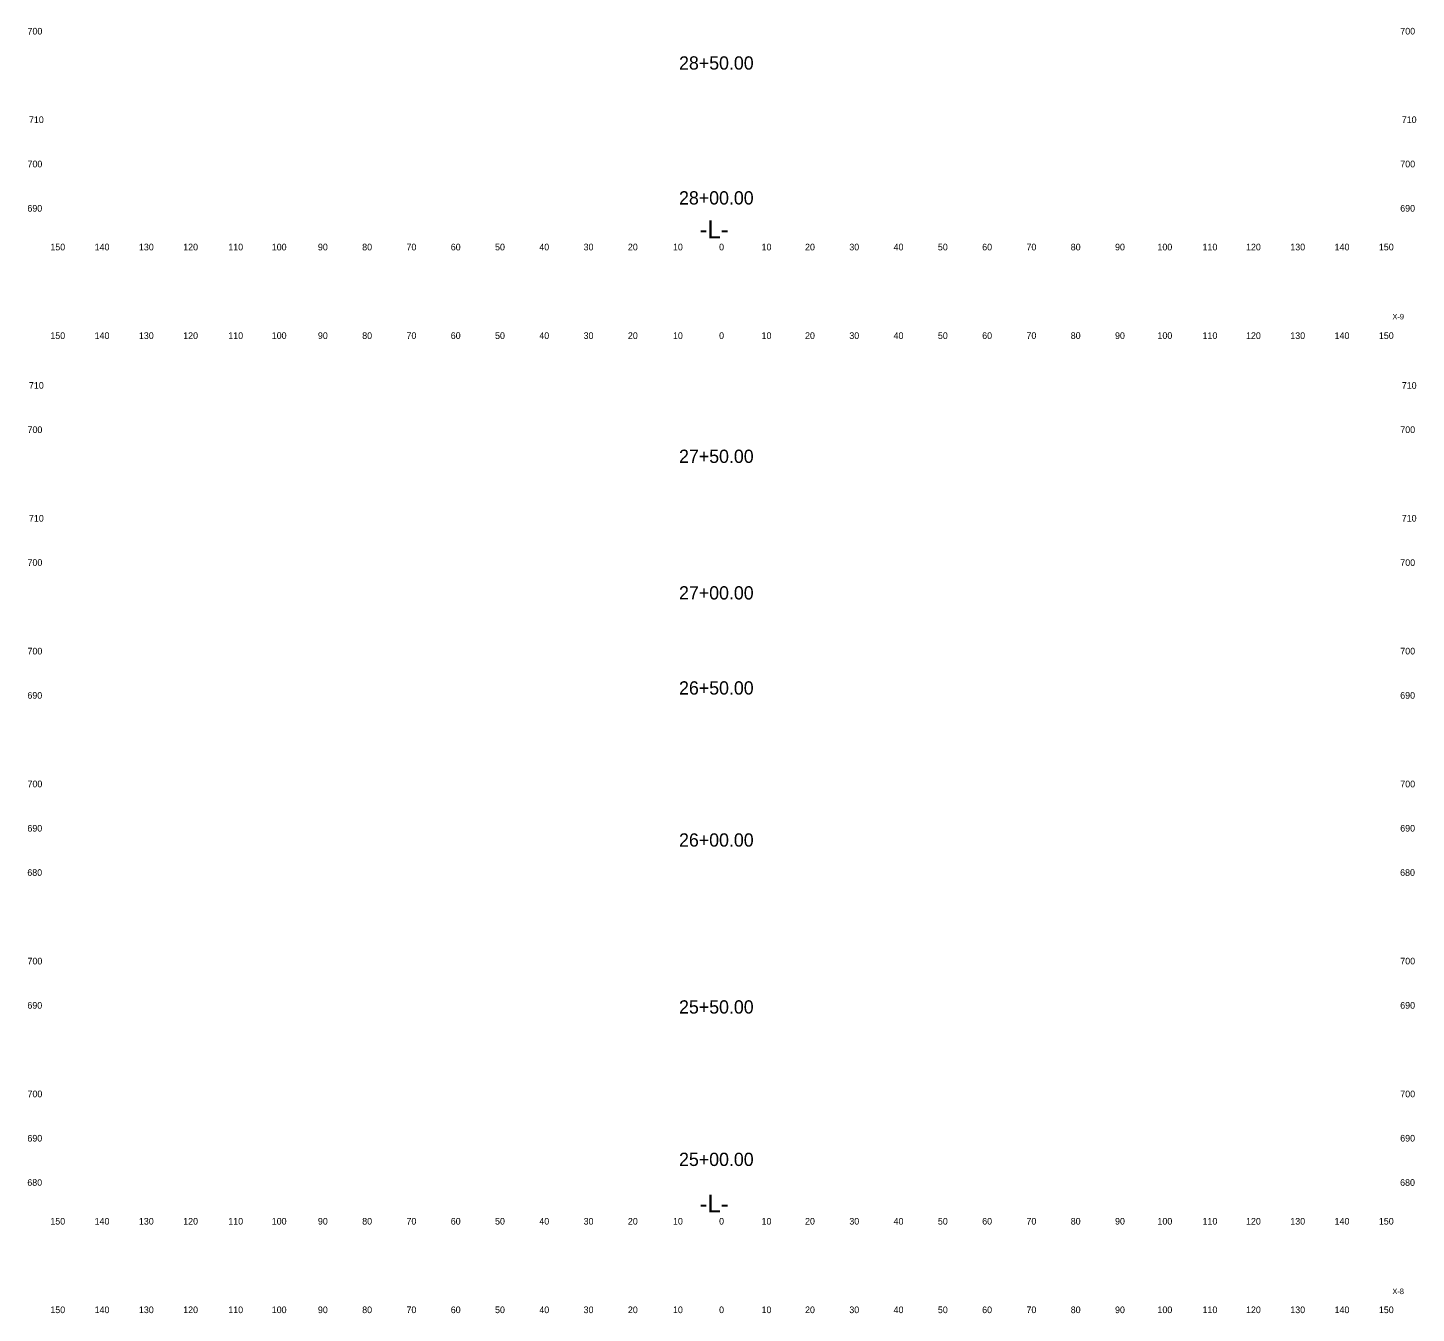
# Model space of a CAD drawing. Extents: x 3 to 317, y 0 to 2407.
# Drawn here: x 3.3 to 316.9, y 1521.2 to 1811.5 of the extents above; entities that cross this region are included whole.
import ezdxf

# ---------------------------------------------------------------- set-up
doc = ezdxf.new("R2010")
doc.units = 0
for name, color, linetype in [('Prop XS Ditch Standard Text', 7, 'Continuous'), ('Prop XS Dump Level', 7, 'Continuous'), ('Prop XS SE Text', 7, 'Continuous'), ('Prop XS Sheet Number', 7, 'Continuous'), ('Prop XS SS Elevation Text', 7, 'Continuous')]:
    doc.layers.add(name, color=color, linetype=linetype)

msp = doc.modelspace()

# ---------------------------------------------------------------- texts
at = {"layer": 'Prop XS Ditch Standard Text'}
for s, p in [('28+50.00', (150.41, 1802.07)), ('28+00.00', (150.41, 1771.61)), ('27+50.00', (150.41, 1713.25)), ('27+00.00', (150.41, 1682.41)), ('26+50.00', (150.41, 1660.94)), ('26+00.00', (150.41, 1626.6)), ('25+50.00', (150.41, 1588.9)), ('25+00.00', (150.41, 1554.48))]:
    msp.add_text(s, height=3, dxfattribs=at).set_placement(p)
at = {"layer": 'Prop XS Dump Level'}
for s, p in [('150', (8.44, 1761.25)), ('140', (18.44, 1761.25)), ('130', (28.44, 1761.25)), ('120', (38.44, 1761.25)), ('110', (48.62, 1761.25)), ('100', (58.44, 1761.25)), ('90', (68.86, 1761.25)), ('80', (78.86, 1761.25)), ('70', (88.86, 1761.25)), ('60', (98.86, 1761.25)), ('50', (108.86, 1761.25)), ('40', (118.86, 1761.25)), ('30', (128.86, 1761.25)), ('20', (138.86, 1761.25)), ('10', (149.04, 1761.25)), ('0', (159.45, 1761.25)), ('10', (169.04, 1761.25)), ('20', (178.86, 1761.25)), ('30', (188.86, 1761.25)), ('40', (198.86, 1761.25)), ('50', (208.86, 1761.25)), ('60', (218.86, 1761.25)), ('70', (228.86, 1761.25)), ('80', (238.86, 1761.25)), ('90', (248.86, 1761.25)), ('100', (258.44, 1761.25)), ('110', (268.62, 1761.25)), ('120', (278.44, 1761.25)), ('130', (288.44, 1761.25)), ('140', (298.44, 1761.25)), ('150', (308.44, 1761.25)), ('150', (8.44, 1741.25)), ('140', (18.44, 1741.25)), ('130', (28.44, 1741.25)), ('120', (38.44, 1741.25)), ('110', (48.62, 1741.25)), ('100', (58.44, 1741.25)), ('90', (68.86, 1741.25)), ('80', (78.86, 1741.25)), ('70', (88.86, 1741.25)), ('60', (98.86, 1741.25)), ('50', (108.86, 1741.25)), ('40', (118.86, 1741.25)), ('30', (128.86, 1741.25)), ('20', (138.86, 1741.25)), ('10', (149.04, 1741.25)), ('0', (159.45, 1741.25)), ('10', (169.04, 1741.25)), ('20', (178.86, 1741.25)), ('30', (188.86, 1741.25)), ('40', (198.86, 1741.25)), ('50', (208.86, 1741.25)), ('60', (218.86, 1741.25)), ('70', (228.86, 1741.25)), ('80', (238.86, 1741.25)), ('90', (248.86, 1741.25)), ('100', (258.44, 1741.25)), ('110', (268.62, 1741.25)), ('120', (278.44, 1741.25)), ('130', (288.44, 1741.25)), ('140', (298.44, 1741.25)), ('150', (308.44, 1741.25)), ('150', (8.44, 1541.25)), ('140', (18.44, 1541.25)), ('130', (28.44, 1541.25)), ('120', (38.44, 1541.25)), ('110', (48.62, 1541.25)), ('100', (58.44, 1541.25)), ('90', (68.86, 1541.25)), ('80', (78.86, 1541.25)), ('70', (88.86, 1541.25)), ('60', (98.86, 1541.25)), ('50', (108.86, 1541.25)), ('40', (118.86, 1541.25)), ('30', (128.86, 1541.25)), ('20', (138.86, 1541.25)), ('10', (149.04, 1541.25)), ('0', (159.45, 1541.25)), ('10', (169.04, 1541.25)), ('20', (178.86, 1541.25)), ('30', (188.86, 1541.25)), ('40', (198.86, 1541.25)), ('50', (208.86, 1541.25)), ('60', (218.86, 1541.25)), ('70', (228.86, 1541.25)), ('80', (238.86, 1541.25)), ('90', (248.86, 1541.25)), ('100', (258.44, 1541.25)), ('110', (268.62, 1541.25)), ('120', (278.44, 1541.25)), ('130', (288.44, 1541.25)), ('140', (298.44, 1541.25)), ('150', (308.44, 1541.25)), ('150', (8.44, 1521.25)), ('140', (18.44, 1521.25)), ('130', (28.44, 1521.25)), ('120', (38.44, 1521.25)), ('110', (48.62, 1521.25)), ('100', (58.44, 1521.25)), ('90', (68.86, 1521.25)), ('80', (78.86, 1521.25)), ('70', (88.86, 1521.25)), ('60', (98.86, 1521.25)), ('50', (108.86, 1521.25)), ('40', (118.86, 1521.25)), ('30', (128.86, 1521.25)), ('20', (138.86, 1521.25)), ('10', (149.04, 1521.25)), ('0', (159.45, 1521.25)), ('10', (169.04, 1521.25)), ('20', (178.86, 1521.25)), ('30', (188.86, 1521.25)), ('40', (198.86, 1521.25)), ('50', (208.86, 1521.25)), ('60', (218.86, 1521.25)), ('70', (228.86, 1521.25)), ('80', (238.86, 1521.25)), ('90', (248.86, 1521.25)), ('100', (258.44, 1521.25)), ('110', (268.62, 1521.25)), ('120', (278.44, 1521.25)), ('130', (288.44, 1521.25)), ('140', (298.44, 1521.25)), ('150', (308.44, 1521.25))]:
    msp.add_text(s, height=1.5, dxfattribs=at).set_placement(p)
at = {"layer": 'Prop XS SE Text'}
for s, p in [('700', (3.28, 1810)), ('700', (313.28, 1810)), ('710', (3.61, 1790)), ('710', (313.61, 1790)), ('700', (3.28, 1780)), ('700', (313.28, 1780)), ('690', (3.26, 1770)), ('690', (313.26, 1770)), ('710', (3.61, 1730)), ('710', (313.61, 1730)), ('700', (3.28, 1720)), ('700', (313.28, 1720)), ('710', (3.61, 1700)), ('710', (313.61, 1700)), ('700', (3.28, 1690)), ('700', (313.28, 1690)), ('700', (3.28, 1670)), ('700', (313.28, 1670)), ('690', (3.26, 1660)), ('690', (313.26, 1660)), ('700', (3.28, 1640)), ('700', (313.28, 1640)), ('690', (3.26, 1630)), ('690', (313.26, 1630)), ('680', (3.24, 1620)), ('680', (313.24, 1620)), ('700', (3.28, 1600)), ('700', (313.28, 1600)), ('690', (3.26, 1590)), ('690', (313.26, 1590)), ('700', (3.28, 1570)), ('700', (313.28, 1570)), ('690', (3.26, 1560)), ('690', (313.26, 1560)), ('680', (3.24, 1550)), ('680', (313.24, 1550))]:
    msp.add_text(s, height=1.5, dxfattribs=at).set_placement(p)
at = {"layer": 'Prop XS Sheet Number'}
for s, p in [('X-9', (311.5, 1745.66)), ('X-8', (311.5, 1525.55))]:
    msp.add_text(s, height=1.25, dxfattribs=at).set_placement(p)
at = {"layer": 'Prop XS SS Elevation Text'}
for p in [(155.06, 1764), (155.06, 1544)]:
    msp.add_text('-L-', height=4, dxfattribs=at).set_placement(p)

doc.saveas('drawing.dxf')
